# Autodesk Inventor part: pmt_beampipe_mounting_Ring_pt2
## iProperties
Shininess: 64.0
Length Units: 11269
Angle Units: 11279
Time Units: 11290
Mass Units: 11283
Length Display Precision: 3
Angle Display Precision: 2
Compacted: True
Part Number: pmt_beampipe_mounting_Ring_pt2
Document SubType Name: Modeling
Created: 2004-08
Designer: John Blackburn
Manufacturer: Standard
Standards Organization: Custom
Material: Aluminum-6061
Density: 0.0
Volumn: 0.0
Area: 0.0
PropertySet Name: Model Information
Control State: 0
Master: False
Checked Out: False
Author: John Blackburn
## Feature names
1. Extrusion1
2. Extrusion3
3. Hole1
4. Extrusion4
5. Hole2
6. Extrusion5
7. Split1
8. Extrusion6
9. Extrusion7
10. Hole3
11. Hole4
12. Hole5
